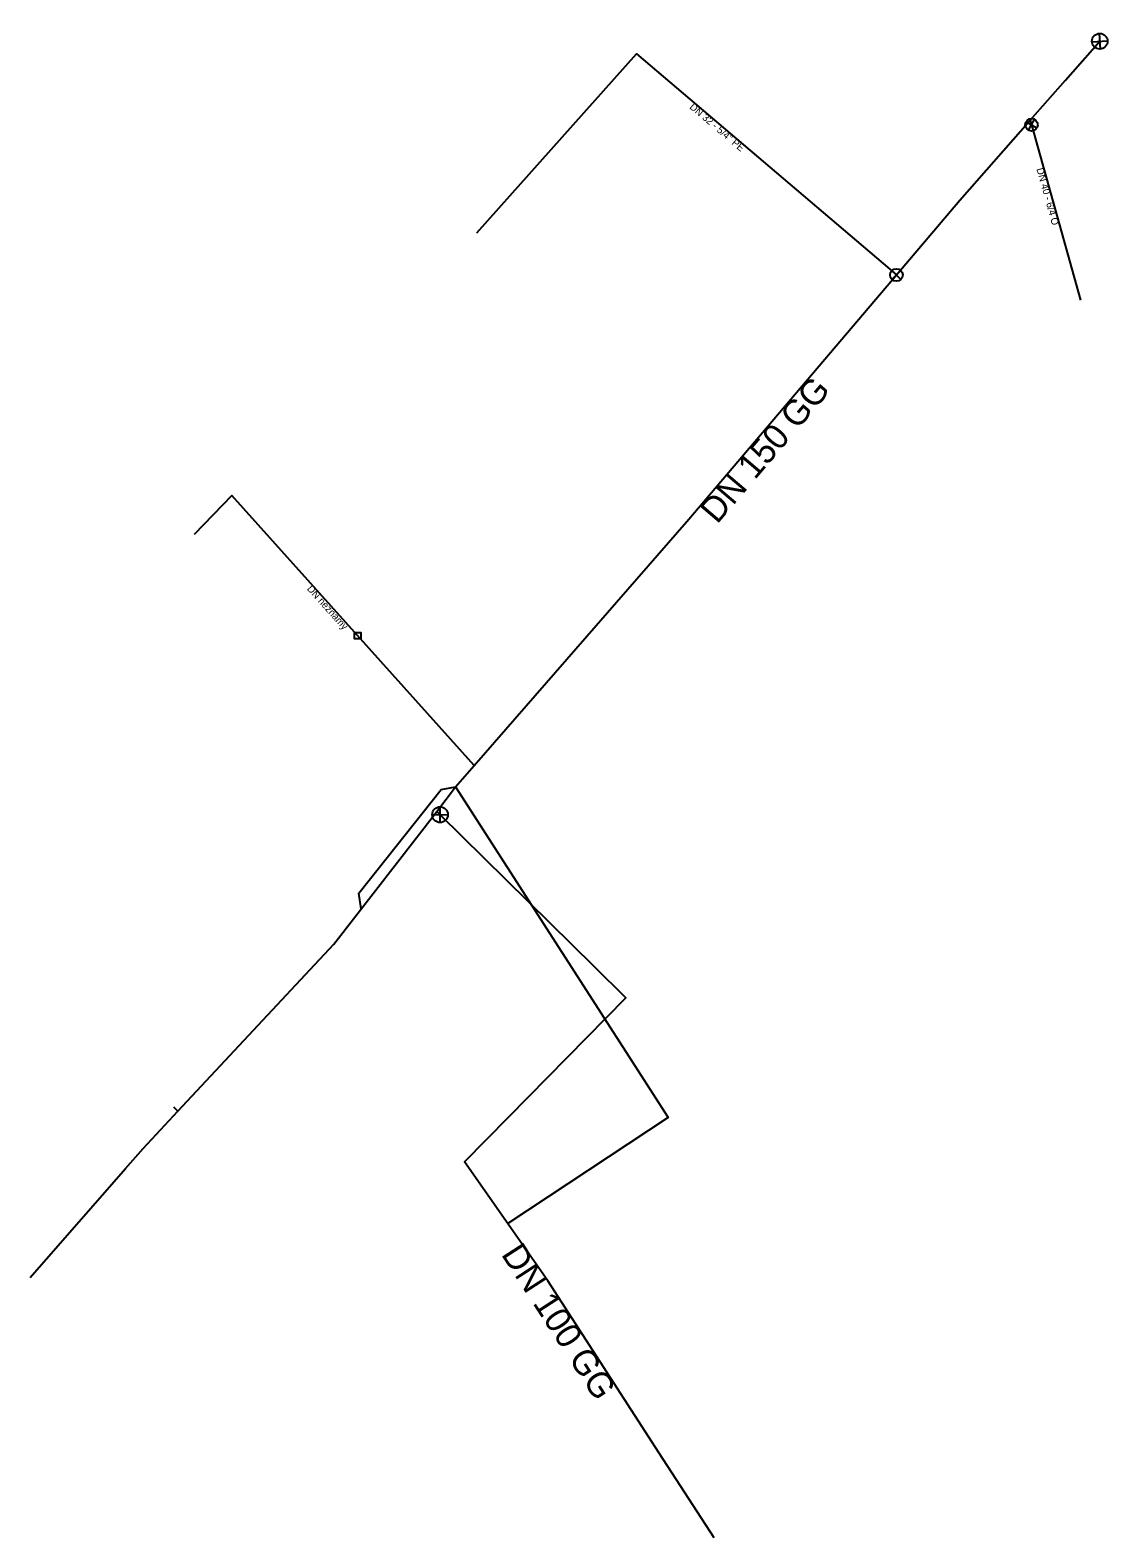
# Model space of a CAD drawing. Extents: x -483422.7 to -483354, y -1126352.5 to -1126256.8.
import ezdxf

# ---------------------------------------------------------------- set-up
doc = ezdxf.new("R2010")
doc.units = 0
for name, color, linetype in [('_pripojka_prevzato_z_dokumentace_', 7, 'Continuous'), ('_pripojka_priblizne_', 7, 'Continuous'), ('_voda_projekt_smvak_', 7, 'Continuous'), ('_voda_smvak_prevzato_z_dokumentace_', 7, 'Continuous'), ('Default', 7, 'Continuous'), ('MoLevel 27', 7, 'Continuous'), ('MoLevel 32', 7, 'Continuous'), ('MoLevel 42', 7, 'Continuous'), ('MoLevel 46', 7, 'Continuous'), ('MoLevel 53', 7, 'Continuous'), ('MoLevel 55', 7, 'Continuous')]:
    doc.layers.add(name, color=color, linetype=linetype)

# ---------------------------------------------------------------- blocks, each defined once
blk = doc.blocks.new('_uzaver_')
at = {"layer": 'Default'}
for p, q in [((-0.000035, -0.000035), (0.000035, 0.000035)), ((0.000035, -0.000035), (-0.000035, 0.000035))]:
    blk.add_line(p, q, dxfattribs=at)
for radius in [0.00005, 0.0000025]:
    blk.add_circle((0, 0), radius, dxfattribs=at)
blk = doc.blocks.new('_uzaver_pripojka_')
at = {"layer": 'Default'}
for p, q in [((-0.000035, -0.000035), (0.000035, 0.000035)), ((0.000035, -0.000035), (-0.000035, 0.000035))]:
    blk.add_line(p, q, dxfattribs=at)
for radius in [0.00005, 0.0000025]:
    blk.add_circle((0, 0), radius, dxfattribs=at)
blk = doc.blocks.new('_poklop_voda_')
at = {"layer": 'Default'}
blk.add_lwpolyline([(-0.00002, 0.00002), (0.00002, 0.00002), (0.00002, -0.00002), (-0.00002, -0.00002), (-0.00002, 0.00002)], dxfattribs=at)

msp = doc.modelspace()

# ---------------------------------------------------------------- linework, layer by layer
at = {"layer": '_pripojka_prevzato_z_dokumentace_'}
for p, q in [((-483359.171, -1126262.502), (-483359.091, -1126262.788)), ((-483413.305, -1126325.418), (-483413.56, -1126325.18))]:
    msp.add_line(p, q, dxfattribs=at)
for points in [[(-483394.317, -1126269.651), (-483384.188, -1126258.27), (-483367.673, -1126272.323)], [(-483394.485, -1126303.474), (-483401.89, -1126295.22), (-483409.872, -1126286.322), (-483412.27, -1126288.807)]]:
    msp.add_lwpolyline(points, dxfattribs=at)
at = {"layer": '_pripojka_priblizne_'}
msp.add_line((-483359.091, -1126262.788), (-483355.978, -1126273.93), dxfattribs=at)
at = {"layer": '_voda_projekt_smvak_'}
for points in [[(-483401.669, -1126312.579), (-483401.811, -1126311.575), (-483396.582, -1126304.996), (-483395.667, -1126304.831)], [(-483395.667, -1126304.831), (-483382.17, -1126325.822), (-483392.352, -1126332.556)]]:
    msp.add_lwpolyline(points, dxfattribs=at)
at = {"layer": '_voda_smvak_prevzato_z_dokumentace_'}
msp.add_line((-483396.656, -1126306.596), (-483396.87, -1126306.385), dxfattribs=at)
for points in [[(-483396.87, -1126306.385), (-483395.667, -1126304.831), (-483394.485, -1126303.474), (-483380.863, -1126287.838), (-483367.673, -1126272.323), (-483363.635, -1126267.573), (-483359.171, -1126262.502), (-483356.924, -1126259.95), (-483354.754, -1126257.482)], [(-483422.692, -1126335.989), (-483416.64, -1126329.069), (-483415.524, -1126327.793), (-483413.305, -1126325.418), (-483403.408, -1126314.824), (-483396.87, -1126306.385)], [(-483379.242, -1126352.521), (-483382.728, -1126347.135), (-483389.811, -1126336.192), (-483395.095, -1126328.634), (-483392.287, -1126325.785), (-483384.847, -1126318.236), (-483386.864, -1126316.248), (-483393.853, -1126309.359), (-483396.656, -1126306.596)]]:
    msp.add_lwpolyline(points, dxfattribs=at)

# ---------------------------------------------------------------- block references
at = {"layer": 'MoLevel 27', "xscale": 10000, "yscale": 10000}
for p, rotation in [((-483354.754, -1126257.482), -131.313710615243), ((-483396.655, -1126306.596), -44.58758611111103)]:
    msp.add_blockref('_uzaver_', p, dxfattribs=dict(at, rotation=rotation))
at = {"layer": 'MoLevel 42', "xscale": 10000, "yscale": 10000}
msp.add_blockref('_poklop_voda_', (-483401.89, -1126295.22), dxfattribs=at)
at = {"layer": 'MoLevel 53', "xscale": 8000.000000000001, "yscale": 7999.999999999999, "rotation": -73.87718888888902}
msp.add_blockref('_uzaver_pripojka_', (-483359.09, -1126262.787), dxfattribs=at)
at = {"layer": 'MoLevel 53', "xscale": 8000, "yscale": 8000}
msp.add_blockref('_uzaver_pripojka_', (-483367.672, -1126272.323), dxfattribs=at)

# ---------------------------------------------------------------- texts
at = {"layer": 'MoLevel 32'}
msp.add_text('DN 40 - 6/4 O', height=0.455, rotation=285.61001, dxfattribs=at).set_placement((-483358.78, -1126265.591))
at = {"layer": 'MoLevel 46'}
for s, rotation, p in [('DN 150 GG', 49.63064, (-483379.058, -1126288.192)), ('DN 100 GG', 302.91349, (-483392.811, -1126334.51))]:
    msp.add_text(s, height=1.6049, rotation=rotation, dxfattribs=at).set_placement(p)
at = {"layer": 'MoLevel 55'}
for s, rotation, p in [("DN 32 - 5/4'' PE", 319.60544, (-483380.844, -1126261.713)), ('DN neznámý', 311.89387, (-483405.139, -1126292.279))]:
    msp.add_text(s, height=0.455, rotation=rotation, dxfattribs=at).set_placement(p)

doc.saveas('drawing.dxf')
